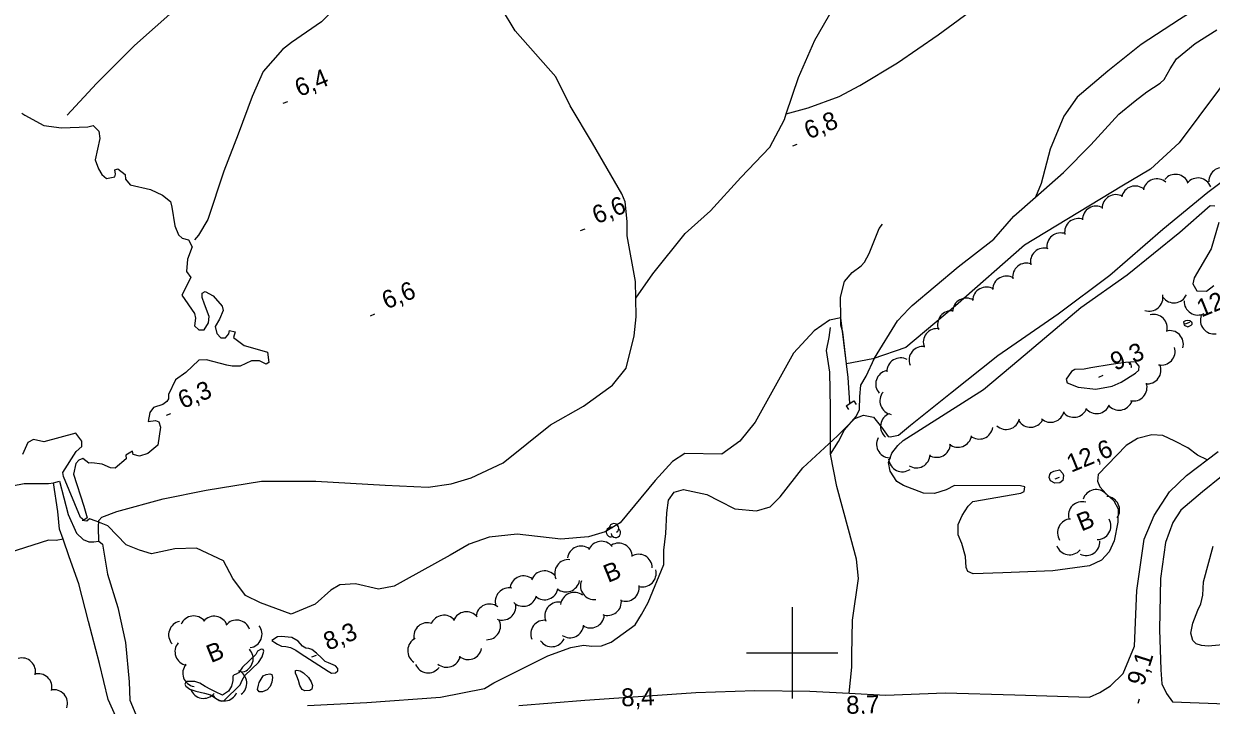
# Model space of a CAD drawing. Extents: x 362852 to 366875, y 5563573 to 5566479.
# Drawn here: x 364831.6 to 365091.9, y 5564988.5 to 5565137.9 of the extents above; entities that cross this region are included whole.
import ezdxf

# ---------------------------------------------------------------- set-up
doc = ezdxf.new("R2010")
doc.units = 0
for name, color, linetype in [('Niveau 1', 7, 'Continuous'), ('Niveau 19', 7, 'Continuous'), ('Niveau 2', 7, 'Continuous'), ('Niveau 21', 7, 'Continuous'), ('Niveau 22', 7, 'Continuous'), ('Niveau 26', 7, 'Continuous'), ('Niveau 3', 7, 'Continuous'), ('Niveau 4', 7, 'Continuous'), ('Niveau 44', 7, 'Continuous'), ('Niveau 61', 7, 'Continuous'), ('Niveau 7', 7, 'Continuous')]:
    doc.layers.add(name, color=color, linetype=linetype)

msp = doc.modelspace()

# ---------------------------------------------------------------- linework, layer by layer
at = {"layer": 'Niveau 1'}
for points in [[(365024.31, 5565046.54), (365041.98, 5565057.69), (365049.68, 5565064.22), (365063.27, 5565075.67), (365073.43, 5565082.84), (365085.02, 5565092.22), (365091.64, 5565098.05), (365092.66, 5565097.98)], [(365093.53, 5565094.37), (365091.83, 5565088.59), (365088.15, 5565082.23), (365087.85, 5565080.87), (365088.71, 5565079.37), (365090.86, 5565079.26), (365092.44, 5565080.54)], [(365064, 5565062.21), (365061.94, 5565062.1), (365061.24, 5565061.69), (365060.1, 5565059.98), (365060.3, 5565059.19), (365062.69, 5565058.2), (365066.56, 5565057.81), (365070.14, 5565058.43), (365072.1, 5565059.36), (365075.26, 5565061.29), (365075.98, 5565061.96), (365076.1, 5565062.87), (365075.24, 5565063.76), (365073.07, 5565063.61), (365069.91, 5565063.17), (365065.5, 5565062.46), (365064, 5565062.21)], [(365091, 5565042.32), (365088.85, 5565043.36), (365086.71, 5565044.95), (365083.89, 5565046.39), (365081.26, 5565047.66), (365078.86, 5565047.78), (365075.73, 5565046.98), (365073.26, 5565045.46), (365067.11, 5565039.08), (365066.96, 5565037.65), (365067.48, 5565036.38), (365068.86, 5565034.84), (365070.49, 5565033.29), (365071.44, 5565031.58), (365071.43, 5565028.6), (365070.63, 5565024.55), (365069.53, 5565022.11), (365067.81, 5565020.28), (365065.21, 5565019.08), (365057.14, 5565017.97), (365046.18, 5565017.53), (365039.71, 5565017.33), (365038.51, 5565017.83), (365038.16, 5565018.68), (365038.03, 5565021.1), (365037.21, 5565023.99), (365036.42, 5565025.89), (365036.38, 5565028.1), (365037.29, 5565030.09), (365038.56, 5565032.11), (365039.61, 5565033.16), (365050.1, 5565035.02), (365050.84, 5565035.33), (365051.02, 5565036.39), (365050.06, 5565036.62), (365035.56, 5565036.69), (365033.74, 5565035.69), (365031.22, 5565034.9), (365028.82, 5565035.02), (365024.43, 5565036.67), (365022.95, 5565037.55), (365021.52, 5565039.81), (365021.1, 5565041.74), (365021.86, 5565043.79), (365023.16, 5565045.45), (365024.31, 5565046.54)], [(365097.62, 5565002), (365091.18, 5565001.44), (365089.75, 5565001.59), (365088.6, 5565001.99), (365087.83, 5565002.66), (365087.38, 5565004.33), (365087.85, 5565006.51), (365088.92, 5565009.31), (365089.58, 5565010.7), (365090.03, 5565012.62), (365090.19, 5565015.53), (365092.28, 5565023.34)]]:
    msp.add_lwpolyline(points, dxfattribs=at)
at = {"layer": 'Niveau 19'}
msp.add_lwpolyline([(364851.76, 5564986.02), (364850.08, 5564989.79), (364848.12, 5564997.63), (364845.77, 5565006.84), (364843.64, 5565015.1), (364841.52, 5565021.06), (364840.16, 5565024.9), (364839.38, 5565027.13), (364839.01, 5565030.96), (364838.04, 5565037.27), (364839.38, 5565037.64), (364841.31, 5565030.35), (364843.09, 5565026.19), (364844.59, 5565024.81), (364845.79, 5565024.32), (364846.95, 5565024.36), (364848.04, 5565024.44), (364848.84, 5565023.84), (364849.94, 5565017.21), (364852.17, 5565009.93), (364853.83, 5565002.23), (364854.68, 5564993.62), (364854.82, 5564989.58), (364856.09, 5564986.44)], dxfattribs=at)
at = {"layer": 'Niveau 2'}
for points in [[(365021.07, 5565047.42), (365021.48, 5565047.34), (365023.3, 5565047.72), (365025.98, 5565049.94), (365034.75, 5565056.92), (365045.1, 5565065.17), (365058.29, 5565074.35), (365069.68, 5565082.78), (365081.24, 5565092.9), (365091.16, 5565100.98), (365103.54, 5565110.31)], [(365086.62, 5565072.83), (365086.21, 5565072.78), (365085.76, 5565072.53), (365085.93, 5565071.8), (365086.75, 5565071.46), (365087.47, 5565071.82), (365087.67, 5565072.08), (365087.69, 5565072.34), (365087.21, 5565072.76), (365086.62, 5565072.83)], [(364893.77, 5564988.45), (364906.77, 5564989.1), (364922.89, 5564990.3), (364932.53, 5564992.18), (364934.63, 5564993.42), (364946.46, 5564999.3), (364951.52, 5565001.15), (364954.29, 5565001.67), (364956.12, 5565001.44), (364958.18, 5565001.54), (364960.34, 5565002.31), (364965.6, 5565006.1), (364967, 5565008.42), (364968.42, 5565010.99), (364971.9, 5565019.39), (364971.86, 5565022.48), (364972.33, 5565026.15), (364972.55, 5565030.71), (364972.91, 5565033.46), (364974.16, 5565035.22), (364976.16, 5565035.8), (364981.32, 5565034.71), (364983.99, 5565033.33), (364987.46, 5565031.53), (364992.21, 5565031.14), (364995.2, 5565032), (364997.41, 5565034.16), (365002.34, 5565040.54), (365009.98, 5565047.55), (365012.09, 5565049.66), (365013.75, 5565051.34), (365015.65, 5565052.13), (365017.83, 5565051.66), (365019.62, 5565049.43), (365021.07, 5565047.42)], [(365058.63, 5565040.09), (365059.34, 5565039.27), (365059.51, 5565038.85), (365059.33, 5565037.78), (365058.68, 5565037.27), (365057.6, 5565037.19), (365056.66, 5565037.67), (365056.36, 5565038.41), (365056.46, 5565039.07), (365056.75, 5565039.56), (365057.38, 5565039.82), (365058.63, 5565040.09)], [(364897.6, 5564998.1), (364896.87, 5564998.8), (364895.72, 5564999.94), (364894.72, 5565000.7), (364894.02, 5565000.91), (364893.36, 5565001.01), (364892.67, 5565001.47), (364891.74, 5565002.51), (364890.29, 5565003.34), (364887.96, 5565003.56), (364887.19, 5565003.49), (364885.97, 5565002.67), (364886.58, 5565002.24), (364887.17, 5565001.87), (364888.04, 5565001.42), (364888.99, 5565001.37), (364890.06, 5565001.19), (364891.19, 5565000.55), (364892.15, 5564999.89), (364898.29, 5564995.97), (364899.03, 5564995.53), (364899.88, 5564995.57), (364900.38, 5564996.02), (364900.41, 5564996.53), (364899.92, 5564997.14), (364898.34, 5564997.79), (364897.6, 5564998.1)], [(364882.41, 5564999.59), (364879.51, 5564996.84), (364878.94, 5564995.98), (364878.6, 5564995.59), (364878.09, 5564995.32), (364877.67, 5564995.14), (364877.42, 5564994.85), (364877.37, 5564993.9), (364877.13, 5564992.68), (364876.46, 5564991.6), (364875.09, 5564990.72), (364873.6, 5564991.47), (364872.58, 5564991.98), (364871.32, 5564992.64), (364870.16, 5564993.34), (364869.03, 5564993.68), (364867.36, 5564993.67), (364866.98, 5564993.39), (364866.83, 5564993.15), (364867.08, 5564992.69), (364867.98, 5564992.01), (364869.27, 5564991.61), (364871.14, 5564991.14), (364872.52, 5564990.78), (364873.53, 5564990.14), (364874.39, 5564989.56), (364874.95, 5564989.42), (364875.52, 5564989.53), (364879, 5564992.96), (364879.44, 5564994.01), (364880.02, 5564995), (364882.98, 5564997.9), (364883.84, 5564999.12), (364884.21, 5565000.33), (364884.04, 5565000.75), (364883.58, 5565000.81), (364882.77, 5565000.36), (364882.41, 5564999.59)], [(364892.16, 5564996.03), (364892.9, 5564995.59), (364893.99, 5564994.6), (364894.56, 5564993.66), (364894.86, 5564992.79), (364894.73, 5564992.05), (364894.25, 5564991.73), (364893.16, 5564991.65), (364892.61, 5564991.92), (364892.11, 5564992.83), (364891.8, 5564993.89), (364891.41, 5564994.84), (364891.12, 5564995.53), (364891.14, 5564996.1), (364891.4, 5564996.21), (364892.16, 5564996.03)], [(364884.72, 5564995.25), (364885.47, 5564995.37), (364885.97, 5564995.21), (364886.06, 5564994.56), (364885.91, 5564993.56), (364885.56, 5564992.61), (364884.91, 5564991.91), (364883.87, 5564991.42), (364883.18, 5564991.44), (364882.83, 5564991.98), (364883, 5564992.92), (364883.15, 5564993.48), (364884.05, 5564994.91), (364884.72, 5564995.25)]]:
    msp.add_lwpolyline(points, dxfattribs=at)
at = {"layer": 'Niveau 21'}
for points in [[(364940.08, 5564988.46), (364954.57, 5564989.62), (364968.4, 5564990.57), (364978.88, 5564991.26), (364991.79, 5564991.71), (365003.89, 5564991.61), (365012.48, 5564991.15), (365020.45, 5564990.72), (365033.57, 5564991.25), (365048.82, 5564990.81), (365065.2, 5564990.27), (365067.42, 5564991.26), (365069.78, 5564992.73), (365072.58, 5564995.45), (365075.03, 5565001.45), (365075.54, 5565013.66), (365077.19, 5565024.9), (365079.39, 5565030.1), (365082.74, 5565035.32), (365086.49, 5565038.87), (365093.41, 5565044.16)], [(365098.27, 5565042.02), (365089.95, 5565035.28), (365085.18, 5565031.29), (365083.44, 5565028.59), (365081.85, 5565024.21), (365080.76, 5565016.31), (365080.57, 5565005.1), (365080.86, 5564996.28), (365081.06, 5564993.19), (365082.06, 5564991.06), (365083.38, 5564989.28), (365095.1, 5564988.79)]]:
    msp.add_lwpolyline(points, dxfattribs=at)
at = {"layer": 'Niveau 22'}
for points in [[(364992.15, 5565262.21), (364989.81, 5565257.24), (364988.41, 5565254.87), (364981.86, 5565248.39), (364973.47, 5565240.25), (364968.42, 5565234.35), (364963.18, 5565229.06), (364959.61, 5565226.31), (364952.85, 5565221.44), (364946.31, 5565216.61), (364939.76, 5565211.76), (364932.23, 5565205.57), (364929.89, 5565203.64), (364919.45, 5565193.79), (364907.72, 5565182.84), (364892.57, 5565167.93), (364881.21, 5565156.97), (364870.09, 5565145.85), (364855.84, 5565133.18), (364847.47, 5565124.8), (364841.07, 5565117.87)], [(364932.23, 5565205.57), (364928.37, 5565197.54), (364924.58, 5565192.43), (364922.44, 5565187.44), (364919.44, 5565179.67), (364916.8, 5565172.73), (364913.09, 5565167.59), (364907.81, 5565159.68), (364904.41, 5565153.61), (364903.27, 5565149.91), (364902.2, 5565146.85), (364899.1, 5565140.6), (364896.83, 5565138.36), (364890.28, 5565133.79), (364888.29, 5565132.28), (364884.01, 5565127.47), (364881.6, 5565121.93), (364878.59, 5565113.72), (364875.39, 5565105.62), (364871.89, 5565094.97), (364869.87, 5565091.59), (364868.95, 5565090.52)], [(364998.72, 5565118.18), (365003.52, 5565119.46), (365010.31, 5565121.95), (365014.87, 5565124.4), (365023.12, 5565129.36), (365032.01, 5565135.52), (365041.11, 5565142.14), (365046.22, 5565146.74), (365049.14, 5565152.85), (365050.23, 5565157.1), (365051.13, 5565164.24), (365051.02, 5565166.62), (365051.18, 5565167.43), (365052.37, 5565169.04), (365054.26, 5565170.63), (365054.95, 5565171.97), (365055.43, 5565174.41), (365054.89, 5565179.6), (365055.31, 5565180.95), (365058.39, 5565186.58)], [(364965.73, 5565077.76), (364969.45, 5565083.07), (364976.58, 5565091.91), (364982.12, 5565096.88), (364988.77, 5565104.23), (364995.08, 5565110.88), (364998.29, 5565116.93), (364998.72, 5565118.18), (365001.43, 5565126.12), (365004.94, 5565134.28), (365009.07, 5565141.39), (365010.05, 5565147.39), (365010.19, 5565156.34), (365010.2, 5565159.09)], [(365103.95, 5565150.95), (365098.12, 5565147.06), (365092.69, 5565143.82), (365084.95, 5565138.82), (365076.5, 5565133.33), (365069.21, 5565127.52), (365062.45, 5565121.81), (365059.54, 5565117.62), (365056.56, 5565110.43), (365054.62, 5565102.86), (365053.34, 5565099.9)], [(364848.04, 5565024.44), (364847.94, 5565027.44), (364847.98, 5565029), (364848.67, 5565029.72), (364851.93, 5565031.01), (364862.12, 5565033.78), (364871.52, 5565035.68), (364883.65, 5565037.59), (364895.59, 5565037.61), (364910.81, 5565036.76), (364920.2, 5565036.28), (364925.26, 5565037.01), (364929.6, 5565038.37), (364936.68, 5565041.67), (364947.05, 5565050), (364954.27, 5565054.1), (364960.6, 5565058.65), (364963.65, 5565062.4), (364965.37, 5565069.51), (364965.82, 5565073.68), (364965.73, 5565077.76), (364965.64, 5565081.43), (364963.86, 5565091.45), (364963.83, 5565094.54), (364963.41, 5565098.9), (364962.69, 5565100.66), (364956.2, 5565111.71), (364951.33, 5565119.9), (364948.19, 5565126.31), (364939.27, 5565136.36), (364936.28, 5565141.34)], [(365008.38, 5565043.58), (365010.14, 5565046.34), (365011.47, 5565048.87), (365014.01, 5565051.84), (365014.74, 5565053.31), (365014.82, 5565056.19), (365015.07, 5565058.7), (365016.25, 5565060.66), (365018.06, 5565064.58), (365023.09, 5565072.8), (365025.58, 5565075.44), (365026.28, 5565076.11), (365036.39, 5565084.64), (365044.18, 5565090.71), (365048.63, 5565095.72), (365053.34, 5565099.9), (365059.5, 5565105.31), (365065.49, 5565111.39), (365071.64, 5565118.09), (365075.21, 5565121), (365077.74, 5565122.98), (365080.65, 5565124.92), (365081.58, 5565125.68), (365082.85, 5565128.01), (365084.24, 5565130.2), (365088.37, 5565133.58), (365093.08, 5565136.58)], [(365012.48, 5564991.15), (365013.07, 5564996.82), (365013.11, 5564999.44), (365013.22, 5565007.17), (365014.56, 5565016.3), (365014.12, 5565020.52), (365012.34, 5565027.04), (365009.8, 5565036.48), (365008.38, 5565043.58), (365008.41, 5565053.68), (365008.25, 5565061.49), (365007.51, 5565066.26), (365008.14, 5565069.12), (365008.43, 5565071.29)], [(364826.78, 5565036.16), (364831.64, 5565037.11), (364834.94, 5565037.1), (364837, 5565037.15), (364838.04, 5565037.27)], [(364840.16, 5565024.9), (364838.64, 5565024.65), (364836.94, 5565024.69), (364826.69, 5565021.38), (364816.18, 5565019.84), (364809.9, 5565019.17), (364807.96, 5565018.74), (364806, 5565017.93), (364803.69, 5565016.6), (364801.92, 5565015.93), (364797.49, 5565015.22), (364793.05, 5565014.69), (364790.69, 5565014.09), (364788.98, 5565013.69), (364786.99, 5565012.69), (364783.93, 5565009.69), (364778.77, 5565004.52), (364777.03, 5565002.37), (364775.1, 5565001.27), (364774.04, 5565000.59), (364771.8, 5564999.46)]]:
    msp.add_lwpolyline(points, dxfattribs=at)
at = {"layer": 'Niveau 26'}
for p, q in [((365011.81, 5565054.16), (365013.51, 5565055.24)), ((365011.81, 5565054.16), (365012.34, 5565053.32)), ((365013.51, 5565055.24), (365014.04, 5565054.4))]:
    msp.add_line(p, q, dxfattribs=at)
at = {"layer": 'Niveau 3'}
for p, q in [((364888.45, 5565120.47), (364889.41, 5565120.86)), ((365000.12, 5565111.16), (365001.08, 5565111.55)), ((364953.64, 5565092.57), (364954.6, 5565092.96)), ((364907.55, 5565073.89), (364908.51, 5565074.28)), ((365086.19, 5565072.13), (365087.15, 5565072.52)), ((365067.26, 5565060.44), (365068.22, 5565060.83)), ((364862.85, 5565052.06), (364863.81, 5565052.45)), ((365057.66, 5565038.11), (365058.62, 5565038.5)), ((364894.74, 5564999.08), (364895.7, 5564999.47)), ((365075.84, 5564988.94), (365076.16, 5564989.93))]:
    msp.add_line(p, q, dxfattribs=at)
at = {"layer": 'Niveau 4'}
for points in [[(364831.15, 5565118.32), (364831.79, 5565117.84)], [(364831.79, 5565117.84), (364835.93, 5565115.63), (364839.83, 5565115.06), (364845.61, 5565115.34), (364846.74, 5565115.62), (364847.99, 5565114.39), (364848.23, 5565112.75), (364847.23, 5565108.11), (364847.94, 5565106.1), (364848.65, 5565104.84), (364849.67, 5565104.02), (364851.52, 5565104.34), (364851.66, 5565104.9), (364851.5, 5565105.89), (364852.21, 5565106.12), (364853.8, 5565104.85), (364853.83, 5565103.87), (364854.9, 5565102.63), (364859.32, 5565101.54), (364861.99, 5565100.34), (364863.75, 5565098.95), (364864.02, 5565097.69), (364864.65, 5565093.6), (364865.46, 5565091.63), (364866.31, 5565090.93), (364867.65, 5565090.55), (364868.47, 5565089.02), (364867.42, 5565086.29), (364867.23, 5565083.59), (364868.21, 5565082.26), (364866.21, 5565078.38), (364868.99, 5565074.37), (364869.22, 5565073.35), (364868.97, 5565071.69), (364869.91, 5565070.77), (364871.13, 5565070.84), (364872.06, 5565072.34), (364872.23, 5565073.72), (364871.19, 5565076.4), (364870.68, 5565077.93), (364870.67, 5565078.86), (364871.29, 5565079.18), (364873.1, 5565078.25), (364875.08, 5565076.01), (364875.29, 5565075.05), (364874.46, 5565073.15), (364873.5, 5565071.57), (364873.9, 5565069.99), (364874.78, 5565069.05), (364875.76, 5565069.08), (364876.52, 5565069.96), (364876.65, 5565070.69), (364877.91, 5565070.35), (364877.54, 5565069.14), (364879.89, 5565067.37), (364883.25, 5565066.45), (364885.01, 5565065.94), (364885.26, 5565063.68), (364884.67, 5565063.31), (364883.2, 5565064.01), (364881.45, 5565064.03), (364878.97, 5565062.82), (364877.22, 5565062.85), (364876.08, 5565063.06), (364871.61, 5565064.26), (364869.9, 5565064.17), (364867.11, 5565061.46), (364864.8, 5565059.83), (364863.31, 5565056.66), (364863.27, 5565055.71), (364862.89, 5565055.12), (364862.07, 5565054.41), (364860.02, 5565053.81), (364859.17, 5565052.71), (364858.82, 5565050.7), (364860.46, 5565050.94), (364861.13, 5565050.66), (364861.51, 5565049.45), (364860.97, 5565045.49), (364858.78, 5565043.72), (364856.93, 5565043.08), (364855.52, 5565043.49), (364855.42, 5565044.19), (364853.96, 5565043.34), (364854.01, 5565042.49), (364851.6, 5565040.5), (364850.6, 5565040.52), (364848.75, 5565041.38), (364846.48, 5565041.62), (364845.81, 5565041.59), (364844.51, 5565042.61), (364843.61, 5565042.24), (364842.99, 5565041.48), (364842.46, 5565039.15), (364844.74, 5565032.13), (364845.48, 5565029.58), (364844.7, 5565029.07), (364843.97, 5565029.63), (364840.24, 5565038.67), (364840.12, 5565039.55), (364843.03, 5565044.11)], [(365012.65, 5565054.7), (365012.28, 5565060.37), (365011.92, 5565063.35), (365011.09, 5565070.26), (365010.69, 5565071.83), (365010.66, 5565073.46), (365010.57, 5565078), (365011.51, 5565081.43), (365013.14, 5565083.35), (365015.12, 5565084.85), (365015.85, 5565085.65), (365016.86, 5565087.56), (365019.08, 5565093.01), (365019.84, 5565094.01)], [(364843.03, 5565044.11), (364844.31, 5565045.2), (364844.25, 5565046.42), (364842.98, 5565048.13), (364835.94, 5565046.22), (364833.66, 5565046.77), (364832.46, 5565046.09), (364831.24, 5565043.47)]]:
    msp.add_lwpolyline(points, dxfattribs=at)
at = {"layer": 'Niveau 44'}
for centre, radius, start, end in [((365084.02, 5565101.9), 3, 20.8016, 140.7795), ((365094.35, 5565103.38), 3, 61.9251, 181.903), ((365075.2, 5565099.34), 3, 48.5035, 168.4814), ((365079.95, 5565100.93), 3, 48.5035, 168.4814), ((365088.95, 5565101.1), 3, 20.8016, 140.7795), ((365070.95, 5565097.45), 3, 60.4194, 180.3973), ((365066.63, 5565094.92), 3, 60.4194, 180.3973), ((365062.73, 5565092.21), 3, 69.2626, 189.2406), ((365058.85, 5565089.05), 3, 69.2626, 189.2406), ((365055.23, 5565085.73), 3, 72.5894, 192.5673), ((365051.34, 5565082.42), 3, 68.3727, 188.3506), ((365046.95, 5565079.58), 3, 58.8744, 178.8523), ((365042.57, 5565077.17), 3, 58.8744, 178.8523), ((365038.19, 5565074.75), 3, 58.8744, 178.8523), ((365078.3, 5565077.91), 3, 250.9678, 10.9457), ((365083.7, 5565079.72), 3, 216.2416, 336.2195), ((365088.94, 5565077.05), 3, 177.5411, 297.5191), ((365034.88, 5565071.98), 3, 81.4113, 201.3893), ((365079.25, 5565071.19), 3, 344.8091, 104.7871), ((365092.5, 5565072.9), 3, 159.1116, 279.0895), ((365031.76, 5565068.08), 3, 81.4113, 201.3893), ((365082.78, 5565067.64), 3, 344.8091, 104.7871), ((365028.64, 5565064.17), 3, 81.4113, 201.3893), ((365080.96, 5565066.09), 3, 256.9095, 16.8875), ((365023.77, 5565061.65), 3, 61.4756, 181.4535), ((365077.86, 5565061.97), 3, 263.2099, 23.1878), ((365021.31, 5565058.93), 3, 101.6408, 221.6188), ((365074.8, 5565058.2), 3, 257.8238, 17.8017), ((365022.24, 5565055.22), 3, 140.3336, 260.3116), ((365056.67, 5565053.53), 3, 228.4931, 348.471), ((365061.78, 5565054.63), 3, 219.3171, 339.295), ((365066.73, 5565055.44), 3, 218.62, 338.598), ((365071.67, 5565056.19), 3, 218.62, 338.598), ((365022.37, 5565049.61), 3, 110.8635, 230.8415), ((365046.92, 5565051.96), 3, 227.0293, 347.0072), ((365052.26, 5565052.45), 3, 212.5283, 332.5063), ((365036.36, 5565048.06), 3, 231.1474, 351.1253), ((365041.03, 5565049.86), 3, 231.1474, 351.1253), ((365021.51, 5565045.74), 3, 152.9802, 272.9581), ((365031.69, 5565045.85), 3, 237.6161, 357.594), ((365024.15, 5565042.69), 3, 184.4541, 304.432), ((365027.26, 5565043.54), 3, 237.6161, 357.594), ((365066.63, 5565032.77), 3, 41.8148, 161.7927), ((365063.55, 5565030.12), 3, 74.2906, 194.2685), ((365068.79, 5565031.3), 3, 325.8877, 85.8656), ((365061.17, 5565026.33), 3, 92.6172, 212.5951), ((365066.87, 5565027.81), 3, 269.6369, 29.6149), ((364960.3, 5565026.46), 1.05, 66.2054, 291.894), ((364960.93, 5565027.28), 1.05, 304.3592, 171.8163), ((364961.33, 5565026.31), 1.05, 189.0269, 51.7112), ((364958.19, 5565021.45), 3, 38.2051, 158.183), ((364961.96, 5565021.03), 3, 1.0001, 120.978), ((365064.46, 5565024.31), 3, 243.8475, 3.8254), ((364953.72, 5565020.39), 3, 52.4209, 172.3989), ((364966.33, 5565018.6), 3, 1.0001, 120.978), ((365060.83, 5565024.48), 3, 199.9607, 319.9386), ((364950.94, 5565017.42), 3, 83.4511, 203.429), ((364941.15, 5565013.87), 3, 50.7233, 170.7012), ((364945.7, 5565014.96), 3, 39.1752, 159.1531), ((364967.19, 5565017.43), 3, 254.2329, 14.2109), ((364937.92, 5565011.24), 3, 78.0597, 198.0376), ((364945.73, 5565014.62), 3, 230.1023, 350.0802), ((364950.43, 5565016.34), 3, 230.1023, 350.0802), ((364956.61, 5565014.65), 3, 157.4719, 277.4499), ((364963.49, 5565014.3), 3, 248.4518, 8.4297), ((364941.03, 5565013.19), 3, 226.8232, 346.8012), ((364948.75, 5565008.09), 3, 82.5187, 202.4967), ((364952.22, 5565010.22), 3, 52.3854, 172.3633), ((364959.57, 5565011.19), 3, 248.4518, 8.4297), ((364928.6, 5565005.98), 3, 38.4738, 158.4518), ((364933.68, 5565007.69), 3, 53.6113, 173.5893), ((364936.44, 5565010.16), 3, 248.3415, 8.3194), ((364866.31, 5565003.95), 3, 101.4281, 221.4061), ((364868.8, 5565005.08), 3, 37.3069, 157.2848), ((364873.3, 5565005.01), 3, 20.2899, 140.2679), ((364878.23, 5565004.17), 3, 20.2899, 140.2679), ((364880.79, 5565004.1), 3, 277.8601, 37.8381), ((364920.04, 5565003.58), 3, 70.5185, 190.4964), ((364923.65, 5565005.24), 3, 38.4738, 158.4518), ((364933.07, 5565005.87), 3, 268.466, 28.4439), ((364945.71, 5565004.13), 3, 82.5187, 202.4967), ((364951.31, 5565006.29), 3, 235.5417, 355.5197), ((364955.83, 5565008.44), 3, 235.5417, 355.5197), ((364867.7, 5565000.24), 3, 139.963, 259.9409), ((364878.85, 5564998.71), 3, 283.307, 43.2849), ((364918.72, 5565000.45), 3, 117.362, 237.3399), ((364928.98, 5565001.5), 3, 229.6058, 349.5837), ((364947.31, 5565004.33), 3, 214.803, 334.781), ((364831.13, 5564995.87), 3, 346.2613, 106.2393), ((364924.27, 5564999.82), 3, 229.6058, 349.5837), ((364834.74, 5564992.41), 3, 346.2613, 106.2393), ((364869.41, 5564995.54), 3, 139.963, 259.9409), ((364877.45, 5564993.33), 3, 305.7796, 65.7575), ((364920.21, 5564998.6), 3, 202.8963, 322.8743), ((364838.13, 5564988.91), 3, 341.3797, 101.3576), ((364870.97, 5564993), 3, 200.085, 320.0629), ((364875.47, 5564992.43), 3, 216.5509, 336.5288)]:
    msp.add_arc(centre, radius, start, end, dxfattribs=at)
at = {"layer": 'Niveau 61'}
for p, q in [((365000, 5565010), (365000, 5564990)), ((364990, 5565000), (365010, 5565000))]:
    msp.add_line(p, q, dxfattribs=at)
at = {"layer": 'Niveau 7'}
for points in [[(365097.77, 5565129.11), (365084.83, 5565111.84), (365078.55, 5565106.02), (365072.27, 5565102.3), (365050.96, 5565089.4), (365035.84, 5565076.06), (365024.96, 5565066.96), (365017.71, 5565064.47), (365011.92, 5565063.35), (365010.66, 5565073.46), (365008.21, 5565072.96), (365004.85, 5565070.58), (365000.28, 5565065.71), (364991.9, 5565050.56), (364988.51, 5565046.43), (364984.61, 5565043.57), (364976.49, 5565043.69), (364973.74, 5565041.94), (364970, 5565037.78), (364962.29, 5565028.5), (364959.01, 5565026.52), (364955.38, 5565025.39), (364949.31, 5565024.89), (364939.73, 5565026.01), (364933.56, 5565025.32), (364929.23, 5565023.78), (364925, 5565021.41), (364915.41, 5565016.08), (364912.78, 5565014.62), (364909.34, 5565013.94), (364904.28, 5565015.08), (364900.87, 5565014.92), (364898.88, 5565013.72), (364895.42, 5565010.67), (364890.18, 5565008.5), (364883.46, 5565010.94), (364880.18, 5565012.57), (364877.41, 5565016.27), (364875.32, 5565020.13)], [(364875.32, 5565020.13), (364869.44, 5565022.93), (364864.65, 5565022.81), (364859.52, 5565021.69), (364856.96, 5565022.49), (364854, 5565023.63), (364849.98, 5565027.81), (364847.43, 5565028.87), (364845.97, 5565029.38), (364845.38, 5565028.85), (364844.39, 5565029)]]:
    msp.add_lwpolyline(points, dxfattribs=at)

# ---------------------------------------------------------------- texts
at = {"layer": 'Niveau 3'}
for s, rotation, p in [('6,4  ', 22.09, (364891.96, 5565121.83)), ('6,8  ', 22.09, (365003.63, 5565112.52)), ('6,6  ', 22.09, (364957.15, 5565093.93)), ('6,6  ', 22.09, (364911.06, 5565075.25)), ('12,2 ', 22.09, (365089.7, 5565073.49)), ('9,3  ', 22.09, (365070.77, 5565061.8)), ('6,3  ', 22.09, (364866.36, 5565053.42)), ('12,6 ', 22.09, (365061.17, 5565039.47)), ('8,3  ', 22.09, (364898.25, 5565000.44)), ('9,1  ', 72.3703, (365077.04, 5564992.51)), ('8,4  ', 1.9964, (364962.58, 5564988.23)), ('8,7  ', 1.5618, (365011.89, 5564986.6))]:
    msp.add_text(s, height=3.93, rotation=rotation, dxfattribs=at).set_placement(p)
at = {"layer": 'Niveau 44'}
for p in [(365063.41, 5565026.56), (364959.64, 5565015.3), (364872.59, 5564997.72)]:
    msp.add_text('B', height=3.93, rotation=22.09, dxfattribs=at).set_placement(p)

doc.saveas('drawing.dxf')
